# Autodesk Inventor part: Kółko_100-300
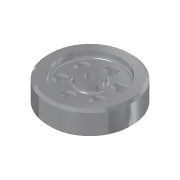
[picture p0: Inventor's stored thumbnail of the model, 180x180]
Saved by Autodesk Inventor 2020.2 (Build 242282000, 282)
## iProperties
Created: 2010-12
Part Number: Kółko_100-300
Document SubType Name: Modeling
Designer: F.Stasiak
Density: 1 g/cm^3
Material: Ogólny
Appearance: Tworzywo sztuczne (białe)
Manager: www.cadconsulting.pl
Company: Fabian Stasiak CAD Consulting
Author: F.Stasiak
Subject: Zbiór ćwiczeń. Autodesk Inventor 2020. Kurs podstawowy
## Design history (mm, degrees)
sketch "Szkic1"
  geometry: C1 r 35 at (0, 0); C2 r 3.75 at (0, 0); 1 further point
  constraints: 2 centre point, 2 coincident
  dimensions: "d0" = 70 diameter of C1; "d1" = 7.5 diameter of C2
extrude "Wyciągnięcie proste1" new body sketch "Szkic1" distance "d2" = 20; taper "d3" = 0 deg
sketch "Szkic2"
  geometry: L1 (-35, 20)-(35, 20) reference; L2 (-35, 0)-(35, 0) reference; L3 (-26, 20)-(-10, 20); L4 (-10, 20)-(-10, 15); L5 (-10, 15)-(-26, 15); L6 (-26, 15)-(-26, 20); L7 (-26, 5)-(-10, 5); L8 (-10, 5)-(-10, 0); L9 (-10, 0)-(-26, 0); L10 (-26, 0)-(-26, 5); L11 (0, -4)-(0, 24) reference; 1 further point
  constraints: 16 end point, 5 collinear, 4 parallel, 2 horizontal, 2 perpendicular
  dimensions: "d4" = 16 distance of L4.end L5.end; "d5" = 5 distance of L3.end L4.end; "d6" = 20 diameter of L4 L11
revolve "Obrót1" sketch "Szkic2" stored, may be unused: angle "d7" = 90 deg
fillet "Zaokrąglenie1" dims "d8" = 2
chamfer "Faza1" distance "d9" = 2; stored, may be unused: second distance "d10" = 2, angle "d11" = 45 deg
sketch "Szkic3"
  geometry: L1 (0, 24)-(0, 12); C1 r 4 at (0, 18); 2 further points
  constraints: 2 end point, 2 vertical alignment, 1 centre point, 1 midpoint, 2 other
  dimensions: "d13" = 8 diameter of C1
extrude "Wyciągnięcie proste2" cut sketch "Szkic3" extent not by distance; stored distance "d14" = 10; taper "d15" = 0 deg
chamfer "Faza2" distance "d16" = 1; stored, may be unused: second distance "d17" = 2, angle "d18" = 45 deg
pattern_circular "Szyk kołowy1" dims angle "d20" = 360 deg
node "Bryła1"
